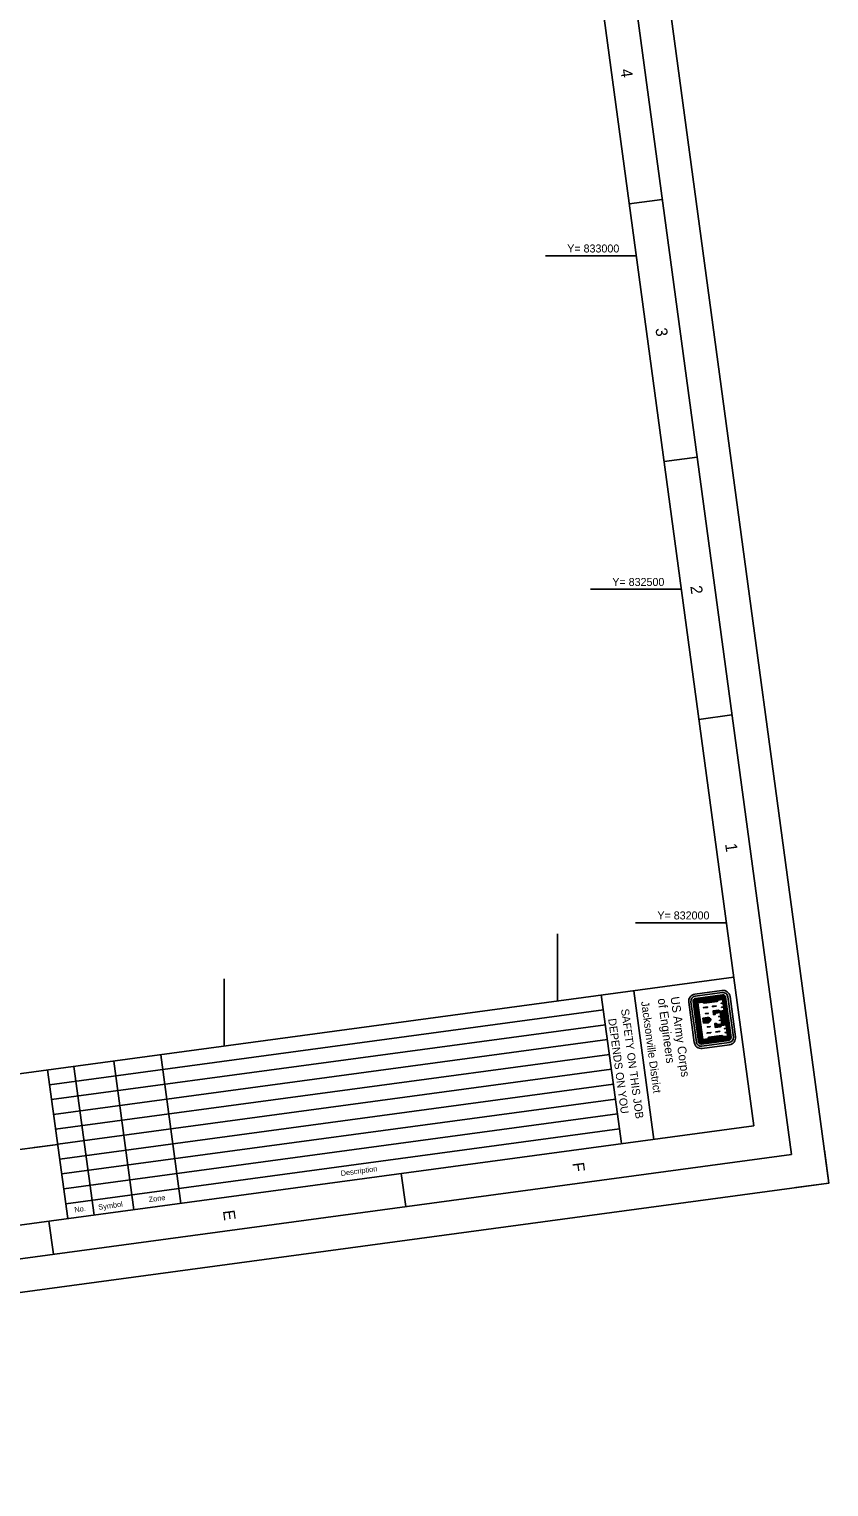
# Model space of a CAD drawing. Extents: x 586448 to 590407, y 831154 to 835970.
# Drawn here: x 589208 to 590407, y 831154 to 833340 of the extents above; entities that cross this region are included whole.
import ezdxf

# ---------------------------------------------------------------- set-up
doc = ezdxf.new("R2010")
doc.units = 0
for name, color, linetype in [('G-ANNO-NPLT', 7, 'Continuous'), ('G-ANNO-TEXT-LOGO', 7, 'Continuous'), ('G-ANNO-TEXT-TTLB', 7, 'Continuous'), ('G-ANNO-TTLB', 7, 'Continuous'), ('V-TOPO-COOR-STAT', 7, 'Continuous')]:
    doc.layers.add(name, color=color, linetype=linetype)

msp = doc.modelspace()

# ---------------------------------------------------------------- linework, layer by layer
at = {"layer": 'G-ANNO-NPLT'}
msp.add_lwpolyline([(589817.4, 835970.1), (590406.9, 831609.7), (587037.5, 831154.3), (586448.1, 835514.6)], close=True, dxfattribs=at)
msp.add_lwpolyline([(590357.3, 831603), (590406.9, 831609.7), (590400.2, 831659.3)], dxfattribs=at)
at = {"layer": 'G-ANNO-TEXT-LOGO'}
for p, q in [((590246.6, 831898.5), (590206, 831893)), ((590196.7, 831881), (590204.9, 831820.7)), ((590208.2, 831821.2), (590200, 831881.4)), ((590211.6, 831821.6), (590203.5, 831881.9)), ((590212.4, 831821.7), (590204.3, 831882)), ((590213.3, 831821.9), (590205.2, 831882.1)), ((590214.2, 831822), (590206.1, 831882.2)), ((590206.4, 831889.9), (590247.1, 831895.3)), ((590247.5, 831891.9), (590206.9, 831886.4)), ((590215, 831822.1), (590206.9, 831882.3)), ((590247.7, 831891), (590207, 831885.5)), ((590247.8, 831890.2), (590207.1, 831884.7)), ((590247.9, 831889.3), (590207.3, 831883.8)), ((590248, 831888.4), (590207.4, 831882.9)), ((590248.1, 831887.5), (590207.8, 831882.1)), ((590215.8, 831822.6), (590207.8, 831882.1)), ((590248.2, 831886.7), (590208.8, 831881.4)), ((590216.6, 831823.5), (590208.8, 831881.4)), ((590239.7, 831884.9), (590218.9, 831882.1)), ((590238.9, 831883.9), (590220, 831881.3)), ((590256.8, 831827.7), (590248.7, 831888)), ((590257.7, 831827.9), (590249.6, 831888.1)), ((590258.5, 831828), (590250.4, 831888.2)), ((590259.4, 831828.1), (590251.2, 831888.3)), ((590260.3, 831828.2), (590252.1, 831888.5)), ((590255.5, 831888.9), (590263.7, 831828.7)), ((590266.8, 831829.1), (590258.7, 831889.3)), ((590218, 831857.2), (590224.7, 831858.1)), ((590218, 831857.2), (590219.1, 831849.3)), ((590218.1, 831856.4), (590224.8, 831857.3)), ((590218.2, 831855.5), (590224.9, 831856.4)), ((590218.4, 831854.6), (590225, 831855.5)), ((590218.5, 831853.8), (590225.1, 831854.7)), ((590245.6, 831866.3), (590248, 831847.8)), ((590246.4, 831866.4), (590248.9, 831848)), ((590247.2, 831866.5), (590249.7, 831848.1)), ((590248.1, 831866.6), (590250.6, 831848.2)), ((590249, 831866.8), (590251.5, 831848.3)), ((590249.8, 831866.9), (590252.3, 831848.4)), ((590250.7, 831867), (590253.2, 831848.5)), ((590218.6, 831852.7), (590225.3, 831853.6)), ((590218.7, 831851.9), (590225.4, 831852.8)), ((590218.9, 831851), (590225.5, 831851.9)), ((590219, 831850.1), (590225.6, 831851)), ((590219.1, 831849.3), (590225.7, 831850.2)), ((590256.3, 831827.2), (590215.7, 831821.7)), ((590256.2, 831828.1), (590215.8, 831822.6)), ((590256.4, 831826.3), (590215.8, 831820.8)), ((590256.5, 831825.5), (590215.9, 831820)), ((590256.6, 831824.6), (590216, 831819.1)), ((590256.8, 831823.7), (590216.1, 831818.2)), ((590256.1, 831828.9), (590216.6, 831823.5)), ((590257.2, 831820.3), (590216.6, 831814.8)), ((590217, 831811.6), (590257.7, 831817.1)), ((590247.2, 831828.4), (590226.6, 831825.6)), ((590246.3, 831829.2), (590227.4, 831826.6))]:
    msp.add_line(p, q, dxfattribs=at)
for points in [[(590248.3, 831886), (590240.5, 831885), (590239, 831883.1), (590220.1, 831880.5), (590218.1, 831881.9), (590209.5, 831880.8), (590217.1, 831824.3), (590225.7, 831825.5), (590227.3, 831827.5), (590246.2, 831830), (590248.1, 831828.5), (590256, 831829.5), (590255, 831837), (590254.2, 831842.7), (590253.5, 831848.1), (590245.6, 831847), (590244.2, 831844.9), (590237.3, 831844), (590236.7, 831848.1), (590237.4, 831848.2), (590239.4, 831846.7), (590247.2, 831847.7), (590246.1, 831855.2), (590245.4, 831860.9), (590244.7, 831866.2), (590236.9, 831865.1), (590235.4, 831863.1), (590234.7, 831863), (590234.1, 831867.2), (590241.1, 831868.1), (590243, 831866.5), (590250.8, 831867.6), (590249.8, 831875), (590249, 831880.8), (590248.3, 831886)], [(590247.5, 831885.1), (590241, 831884.2), (590239.5, 831882.2), (590219.8, 831879.6), (590217.8, 831881.1), (590210.5, 831880.1), (590217.9, 831825.2), (590225.2, 831826.2), (590226.8, 831828.3), (590246.4, 831831), (590248.4, 831829.3), (590255, 831830.2), (590254.2, 831835.6), (590251.2, 831835.2), (590251.1, 831835.7), (590254.2, 831836.1), (590253.5, 831841.3), (590250.4, 831840.9), (590250.3, 831841.3), (590253.4, 831841.7), (590252.7, 831847.1), (590246.1, 831846.2), (590244.6, 831844.2), (590236.6, 831843.1), (590235.8, 831848.8), (590237.7, 831849.1), (590239.7, 831847.5), (590246.3, 831848.4), (590245.5, 831853.8), (590242.5, 831853.4), (590242.4, 831853.7), (590245.5, 831854.2), (590244.8, 831859.5), (590241.7, 831859.1), (590241.6, 831859.6), (590244.7, 831860), (590244, 831865.3), (590237.4, 831864.4), (590235.9, 831862.4), (590234, 831862.1), (590233.2, 831867.8), (590241.3, 831868.9), (590243.3, 831867.4), (590249.8, 831868.3), (590249.1, 831873.5), (590246, 831873.1), (590246, 831873.6), (590249, 831874), (590248.3, 831879.4), (590245.2, 831879), (590245.2, 831879.4), (590248.3, 831879.8), (590247.5, 831885.1)], [(590238, 831875.6), (590232.3, 831874.8), (590232.4, 831874.2), (590238.1, 831875), (590238, 831875.6)], [(590224.9, 831873.8), (590219, 831873), (590219.1, 831872.4), (590224.9, 831873.2), (590224.9, 831873.8)], [(590226.1, 831864.7), (590222, 831864.1), (590222.1, 831863.6), (590226.2, 831864.2), (590226.1, 831864.7)], [(590241.4, 831866.7), (590240.8, 831867.2), (590235.1, 831866.4), (590235.4, 831864.5), (590236.5, 831866), (590241.5, 831866.6)], [(590230.1, 831835.2), (590224.2, 831834.4), (590224.2, 831834.9), (590230, 831835.7), (590230.1, 831835.2)], [(590228.9, 831844.2), (590224.8, 831843.7), (590224.7, 831844.2), (590228.8, 831844.7), (590228.9, 831844.2)], [(590243.3, 831837), (590237.5, 831836.2), (590237.4, 831836.7), (590243.2, 831837.5), (590243.3, 831837)], [(590244.1, 831846.3), (590243.7, 831845.7), (590238, 831845), (590237.8, 831846.8), (590239.2, 831845.8), (590244.2, 831846.4)]]:
    msp.add_lwpolyline(points, dxfattribs=at)
for centre, major_axis, start_param, end_param in [((590248.1, 831887.9), (1.4, -10.6), 1.57078, 3.141576), ((590207.4, 831882.4), (-1.4, 10.6), 6.28317, 7.853966), ((590207.4, 831882.4), (-1, 7.42), 6.28317, 7.853966), ((590207.4, 831882.4), (-0.54, 3.98), 6.28317, 7.853966), ((590207.4, 831882.4), (-0.42, 3.12), 6.28317, 7.853966), ((590207.4, 831882.4), (-0.31, 2.26), 6.28317, 7.853966), ((590207.4, 831882.4), (-0.19, 1.4), 6.28317, 7.853966), ((590207.4, 831882.4), (-0.073, 0.541), 6.28317, 7.853966), ((590248.1, 831887.9), (1, -7.42), 1.57078, 3.141576), ((590248.1, 831887.9), (0.54, -3.98), 1.57078, 3.141576), ((590248.1, 831887.9), (0.42, -3.12), 1.57078, 3.141576), ((590248.1, 831887.9), (0.31, -2.26), 1.57078, 3.141576), ((590248.1, 831887.9), (0.19, -1.4), 1.57078, 3.141576), ((590248.1, 831887.9), (0.073, -0.541), 1.57078, 3.141576), ((590224.9, 831852.6), (-0.74, 5.5), 4.985832, 6.214359), ((590224.9, 831852.6), (-0.63, 4.64), 4.947465, 6.21436), ((590224.9, 831852.6), (-0.51, 3.78), 4.947465, 6.21436), ((590224.9, 831852.6), (-0.4, 2.92), 4.947465, 6.21436), ((590224.9, 831852.6), (-0.28, 2.06), 4.947465, 6.214359), ((590224.5, 831855.6), (0.28, -2.06), 0.068794, 1.335689), ((590224.5, 831855.6), (0.4, -2.92), 0.068794, 1.335689), ((590224.5, 831855.6), (0.51, -3.78), 0.068795, 1.335689), ((590224.5, 831855.6), (0.63, -4.64), 0.068795, 1.335689), ((590224.5, 831855.6), (0.74, -5.5), 0.068795, 1.29842), ((590215.5, 831822.2), (1.4, -10.6), 4.712373, 6.28317), ((590215.5, 831822.2), (-1, 7.42), 1.570781, 3.141577), ((590215.5, 831822.2), (0.54, -3.98), 4.712373, 6.28317), ((590215.5, 831822.2), (0.42, -3.12), 4.712373, 6.28317), ((590215.5, 831822.2), (0.31, -2.26), 4.712373, 6.28317), ((590215.5, 831822.2), (0.19, -1.4), 4.712373, 6.28317), ((590215.5, 831822.2), (0.073, -0.541), 4.712373, 6.28317), ((590256.2, 831827.7), (0.073, -0.541), 6.283169, 7.853965), ((590256.2, 831827.7), (0.19, -1.4), 6.283169, 7.853965), ((590256.2, 831827.7), (0.31, -2.26), 6.283169, 7.853965), ((590256.2, 831827.7), (0.42, -3.12), 6.283169, 7.853965), ((590256.2, 831827.7), (0.54, -3.98), 6.283169, 7.853965), ((590256.2, 831827.7), (1, -7.42), 6.28317, 7.853966), ((590256.2, 831827.7), (1.4, -10.6), 6.283169, 7.853965)]:
    msp.add_ellipse(centre, major_axis=major_axis, ratio=0.99964, start_param=start_param, end_param=end_param, dxfattribs=at)
at = {"layer": 'G-ANNO-TTLB'}
for p, q in [((590157, 833084.6), (590107.5, 833077.9)), ((590209.3, 832698.1), (590159.7, 832691.4)), ((590261.5, 832311.6), (590212, 832304.9)), ((590264.2, 831918.4), (587093.1, 831489.8)), ((590114.4, 831898.2), (590144.5, 831675.2)), ((590065.6, 831892.2), (590095.7, 831669.2)), ((590068.7, 831869.5), (589238.3, 831757.2)), ((590071.7, 831847.2), (589241.3, 831734.9)), ((590074.7, 831824.9), (589244.3, 831712.6)), ((590077.7, 831802.6), (589247.3, 831690.3)), ((589334.3, 831792.7), (589364.4, 831569.7)), ((589404.8, 831802.2), (589434.9, 831579.3)), ((589235.3, 831779.3), (589265.5, 831556.4)), ((590080.7, 831780.3), (589250.4, 831668)), ((589274.8, 831784.7), (589304.9, 831561.7)), ((590083.7, 831758), (589253.4, 831645.7)), ((590086.7, 831735.7), (589256.4, 831623.4)), ((590089.8, 831713.4), (589259.4, 831601.1)), ((590092.8, 831691.1), (589262.4, 831578.8)), ((588398.5, 831553.3), (589250.4, 831667.8)), ((589250.4, 831667.8), (589215.3, 831663.1)), ((589772.4, 831574.4), (589765.7, 831624)), ((589243.9, 831503), (589237.2, 831552.5))]:
    msp.add_line(p, q, dxfattribs=at)
for points in [[(586504.3, 835471.7), (587080.4, 831210.5), (590350.6, 831652.6), (589774.6, 835913.8)], [(590294.4, 831695.4), (589741.8, 835783.2), (586570.6, 835354.5), (587123.2, 831266.8)]]:
    msp.add_lwpolyline(points, close=True, dxfattribs=at)
at = {"layer": 'V-TOPO-COOR-STAT'}
for p, q in [((589981.8, 833000), (590118, 833000)), ((590049.4, 832500), (590185.6, 832500)), ((590117, 832000), (590253.2, 832000)), ((590000, 831882.7), (590000, 831983.6)), ((589500, 831815.1), (589500, 831916))]:
    msp.add_line(p, q, dxfattribs=at)

# ---------------------------------------------------------------- texts
at = {"layer": 'G-ANNO-TEXT-TTLB'}
for s, height, rotation, p in [('Jacksonville District', 11.9, 277.6988, (590125.2, 831881.5)), ('of Engineers', 13.086, 277.6988, (590150.2, 831885.9)), ('US Army Corps', 13.086, 277.6988, (590169.4, 831888.5)), ('DEPENDS ON YOU', 11.9, 277.6988, (590075.9, 831855.8)), ('SAFETY ON THIS JOB', 11.9, 277.6988, (590095.1, 831870.2)), ('Description', 8, 7.6988, (589675.3, 831620.2)), ('No.', 8, 7.6988, (589275.9, 831565.7)), ('Symbol', 8, 7.6988, (589311.8, 831569.6)), ('Zone', 8, 7.6988, (589387.3, 831581))]:
    msp.add_text(s, height=height, rotation=rotation, dxfattribs=at).set_placement(p)
at = {"layer": 'G-ANNO-TTLB'}
for s, p in [('4', (590094.2, 833279.2)), ('3', (590146.7, 832891)), ('2', (590199, 832504.5)), ('1', (590251.2, 832118.1)), ('F', (590022.1, 831639.7)), ('E', (589498.1, 831568.1))]:
    msp.add_text(s, height=17.5, rotation=277.6988, dxfattribs=at).set_placement(p)
at = {"layer": 'V-TOPO-COOR-STAT'}
for s, p in [('Y= 833000', (590014.5, 833005)), ('Y= 832500', (590082.1, 832505)), ('Y= 832000', (590149.7, 832005))]:
    msp.add_text(s, height=12, dxfattribs=at).set_placement(p)

doc.saveas('drawing.dxf')
